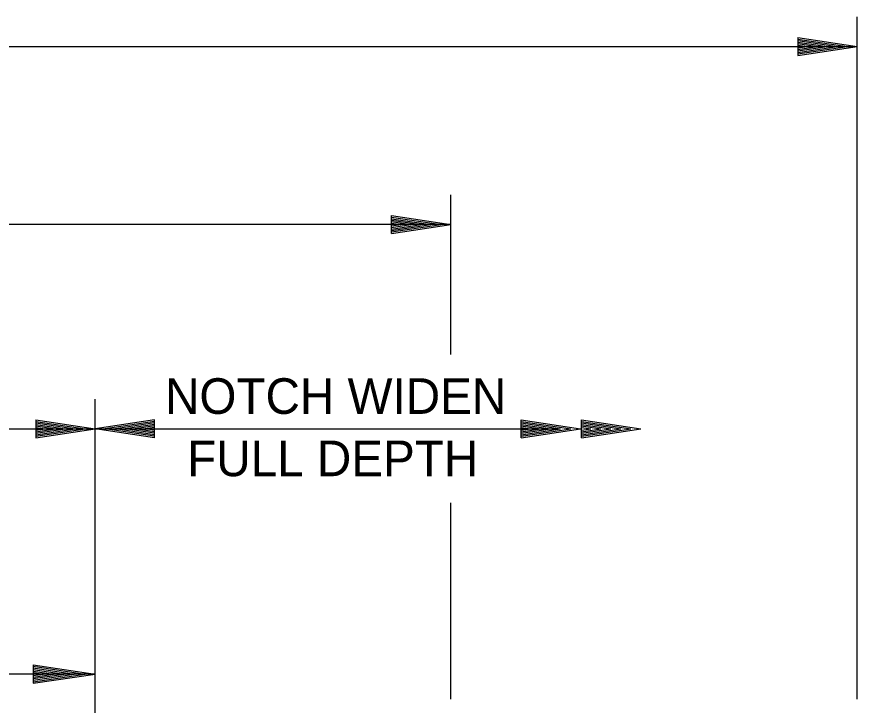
# Model space of a CAD drawing. Extents: x -900 to 15312, y 1857 to 2945.
# Drawn here: x -392.5 to -250.9, y 2300.3 to 2416.2 of the extents above; entities that cross this region are included whole.
import ezdxf

# ---------------------------------------------------------------- set-up
doc = ezdxf.new("R2010")
doc.units = 0
doc.layers.add('R_Annotation', color=7, linetype='Continuous')
doc.layers.add('R_Dimension', color=7, linetype='Continuous')

msp = doc.modelspace()

# ---------------------------------------------------------------- linework, layer by layer
at = {"layer": 'R_Dimension'}
for p, q in [((-250.88, 2301.32), (-250.88, 2416.24)), ((-260.88, 2412.74), (-250.88, 2411.24)), ((-260.88, 2412.74), (-260.88, 2409.74)), ((-260.88, 2412.49), (-252.55, 2411.24)), ((-687.73, 2411.24), (-250.88, 2411.24)), ((-260.88, 2412.23), (-254.27, 2411.24)), ((-260.88, 2411.98), (-255.94, 2411.24)), ((-260.88, 2411.72), (-257.63, 2411.24)), ((-260.88, 2411.47), (-259.3, 2411.24)), ((-260.88, 2409.74), (-250.88, 2411.24)), ((-260.88, 2410.75), (-257.63, 2411.24)), ((-260.88, 2410.24), (-254.27, 2411.24)), ((-260.88, 2409.99), (-252.55, 2411.24)), ((-260.88, 2410.49), (-255.94, 2411.24)), ((-260.88, 2411), (-259.3, 2411.24)), ((-319.31, 2359.34), (-319.31, 2386.24)), ((-329.31, 2382.74), (-319.31, 2381.24)), ((-329.31, 2379.74), (-329.31, 2382.74)), ((-319.31, 2381.24), (-619.31, 2381.24)), ((-329.31, 2382.49), (-320.98, 2381.24)), ((-329.31, 2382.23), (-322.7, 2381.24)), ((-329.31, 2381.98), (-324.36, 2381.24)), ((-329.31, 2381.73), (-326.06, 2381.24)), ((-329.31, 2381.47), (-327.73, 2381.24)), ((-329.31, 2379.74), (-319.31, 2381.24)), ((-329.31, 2380.75), (-326.06, 2381.24)), ((-329.31, 2380.24), (-322.7, 2381.24)), ((-329.31, 2379.99), (-320.98, 2381.24)), ((-329.31, 2380.49), (-324.36, 2381.24)), ((-329.31, 2381), (-327.73, 2381.24)), ((-379.28, 2273.74), (-379.24, 2351.84)), ((-389.24, 2348.34), (-379.24, 2346.84)), ((-389.24, 2348.34), (-389.24, 2345.34)), ((-389.24, 2348.09), (-380.91, 2346.84)), ((-389.24, 2347.83), (-382.63, 2346.84)), ((-389.24, 2347.58), (-384.3, 2346.84)), ((-389.24, 2347.32), (-385.99, 2346.84)), ((-369.24, 2348.34), (-379.24, 2346.84)), ((-369.24, 2348.09), (-377.57, 2346.84)), ((-369.24, 2347.83), (-375.85, 2346.84)), ((-369.24, 2347.58), (-374.19, 2346.84)), ((-369.24, 2347.33), (-372.49, 2346.84)), ((-369.24, 2345.34), (-369.24, 2348.34)), ((-307.48, 2348.34), (-297.48, 2346.84)), ((-307.48, 2345.34), (-307.48, 2348.34)), ((-307.48, 2348.09), (-299.15, 2346.84)), ((-307.48, 2347.83), (-300.87, 2346.84)), ((-307.48, 2347.58), (-302.54, 2346.84)), ((-307.48, 2347.33), (-304.23, 2346.84)), ((-297.32, 2348.34), (-287.32, 2346.84)), ((-297.32, 2345.34), (-297.32, 2348.34)), ((-297.32, 2348.09), (-288.99, 2346.84)), ((-297.32, 2347.83), (-290.71, 2346.84)), ((-297.32, 2347.58), (-292.37, 2346.84)), ((-297.32, 2347.33), (-294.07, 2346.84)), ((-741.93, 2346.84), (-300.92, 2346.84)), ((-389.24, 2347.07), (-387.66, 2346.84)), ((-389.24, 2345.34), (-379.24, 2346.84)), ((-389.24, 2346.35), (-385.99, 2346.84)), ((-389.24, 2345.84), (-382.63, 2346.84)), ((-389.24, 2345.59), (-380.91, 2346.84)), ((-389.24, 2346.09), (-384.3, 2346.84)), ((-389.24, 2346.6), (-387.66, 2346.84)), ((-369.24, 2345.34), (-379.24, 2346.84)), ((-369.24, 2345.59), (-377.57, 2346.84)), ((-369.24, 2345.84), (-375.85, 2346.84)), ((-369.24, 2346.09), (-374.19, 2346.84)), ((-369.24, 2346.35), (-372.49, 2346.84)), ((-369.24, 2347.07), (-370.82, 2346.84)), ((-369.24, 2346.6), (-370.82, 2346.84)), ((-307.48, 2347.07), (-305.9, 2346.84)), ((-307.48, 2345.34), (-297.48, 2346.84)), ((-307.48, 2346.35), (-304.23, 2346.84)), ((-307.48, 2345.84), (-300.87, 2346.84)), ((-307.48, 2345.59), (-299.15, 2346.84)), ((-307.48, 2346.09), (-302.54, 2346.84)), ((-307.48, 2346.6), (-305.9, 2346.84)), ((-297.32, 2347.07), (-295.74, 2346.84)), ((-297.32, 2345.34), (-287.32, 2346.84)), ((-297.32, 2346.35), (-294.07, 2346.84)), ((-297.32, 2345.84), (-290.71, 2346.84)), ((-297.32, 2345.59), (-288.99, 2346.84)), ((-297.32, 2346.09), (-292.37, 2346.84)), ((-297.32, 2346.6), (-295.74, 2346.84)), ((-319.31, 2301.32), (-319.31, 2334.34)), ((-389.67, 2307.09), (-379.27, 2305.53)), ((-389.67, 2307.09), (-389.67, 2303.97)), ((-389.67, 2306.83), (-381, 2305.53)), ((-389.67, 2306.56), (-382.79, 2305.53)), ((-389.67, 2306.3), (-384.52, 2305.53)), ((-379.27, 2305.53), (-593.67, 2305.53)), ((-389.67, 2306.03), (-386.29, 2305.53)), ((-389.67, 2305.77), (-388.03, 2305.53)), ((-389.67, 2303.97), (-379.27, 2305.53)), ((-389.67, 2305.02), (-386.29, 2305.53)), ((-389.67, 2304.5), (-382.79, 2305.53)), ((-389.67, 2304.23), (-381, 2305.53)), ((-389.67, 2304.76), (-384.52, 2305.53)), ((-389.67, 2305.29), (-388.03, 2305.53))]:
    msp.add_line(p, q, dxfattribs=at)

# ---------------------------------------------------------------- texts
at = {"layer": 'R_Annotation'}
for s, p in [('NOTCH WIDEN ', (-367.49, 2349.35)), ('FULL DEPTH', (-363.75, 2338.85))]:
    msp.add_text(s, height=6, dxfattribs=at).set_placement(p)

doc.saveas('drawing.dxf')
